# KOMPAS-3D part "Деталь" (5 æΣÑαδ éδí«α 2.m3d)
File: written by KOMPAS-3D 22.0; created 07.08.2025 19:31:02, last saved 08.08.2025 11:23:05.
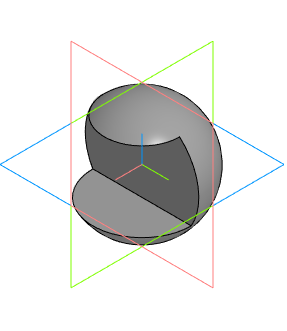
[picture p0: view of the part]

Document properties: Автор: user; Полное имя файла: G:\08 08 пятница\2025 НГ Лаб работы\Лаб 5 Сечения сферы и тора\5 Модели\Сферы Выбор 2.m3d

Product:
- Part/product: Деталь
    Масса: 0.157851

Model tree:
1. Эскиз:1
2. Элемент вращения:1
     Угол 1 = 360
3. Эскиз:2
4. Элемент выдавливания:1
     Расстояние 1 = 20; Расстояние 2 = 20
